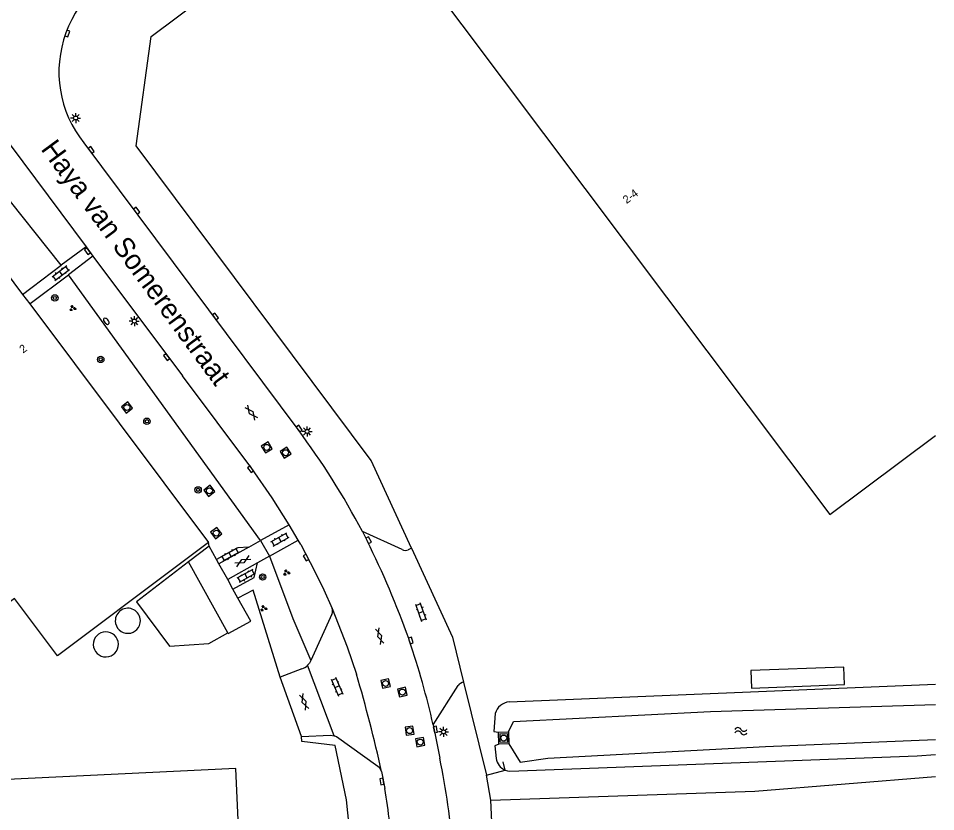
# Model space of a CAD drawing. Extents: x 126000 to 131009, y 393000 to 395500.
# Drawn here: x 130885.3 to 131000, y 393823.1 to 393922.3 of the extents above; entities that cross this region are included whole.
import ezdxf

# ---------------------------------------------------------------- set-up
doc = ezdxf.new("R2010")
doc.units = 0
for name, color, linetype in [('gg-afsc-hekwerk', 7, 'Continuous'), ('gg-anno-huisnummerreeks BGT', 7, 'Continuous'), ('gg-anno-openbare ruimte label', 7, 'Continuous'), ('gg-bbg-bijgebouw', 7, 'Continuous'), ('gg-bbg-gedigitaliseerde bebouwing', 7, 'Continuous'), ('gg-bbg-gedigitaliseerde bijgebouw', 7, 'Continuous'), ('gg-bbg-hoofdgebouw', 7, 'Continuous'), ('gg-bbg-luifel en loopbrug', 7, 'Continuous'), ('gg-bbg-opslagtank', 7, 'Continuous'), ('gg-knt-verharding', 7, 'Continuous'), ('gg-kntw-bovenkant insteek waterloop', 7, 'Continuous'), ('gg-kntw-waterlijn', 7, 'Continuous'), ('gg-kwrk-uitstroombak niveau min 01', 7, 'Continuous'), ('gt-grn-groengrens', 7, 'Continuous'), ('gt-grn-vlakafsluiter', 7, 'Continuous'), ('gt-symb-boom', 7, 'Continuous'), ('gt-symb-brandkraan', 7, 'Continuous'), ('gt-symb-gesloten verharding', 7, 'Continuous'), ('gt-symb-groenvak', 7, 'Continuous'), ('gt-symb-klinker verharding', 7, 'Continuous'), ('gt-symb-kolk', 7, 'Continuous'), ('gt-symb-lichtmast', 7, 'Continuous'), ('gt-symb-rioolschacht', 7, 'Continuous'), ('gt-symb-watersymbool', 7, 'Continuous')]:
    doc.layers.add(name, color=color, linetype=linetype)

# ---------------------------------------------------------------- blocks, each defined once
blk = doc.blocks.new('gt0-BOOM')
at = {"layer": 'gt-symb-boom'}
for radius in [0.4, 0.2]:
    blk.add_circle((0, 0), radius, dxfattribs=at)
blk = doc.blocks.new('gt0-KL1')
at = {"layer": 'gt-symb-klinker verharding'}
for p, q in [((-1.15, 0.3), (1.15, 0.3)), ((-1, -0.3), (-1, 0.3)), ((-0.5, 0.3), (-0.5, 0.45)), ((0, -0.3), (0, 0.3)), ((0.5, 0.3), (0.5, 0.45)), ((1, -0.3), (1, 0.3)), ((-1.15, -0.3), (1.15, -0.3)), ((-0.5, -0.45), (-0.5, -0.3)), ((0.5, -0.45), (0.5, -0.3))]:
    blk.add_line(p, q, dxfattribs=at)
blk = doc.blocks.new('gt0-KOLK')
at = {"layer": 'gt-symb-kolk'}
blk.add_lwpolyline([(0, 0), (0.38, 0), (0.38, 0.4), (-0.37, 0.4), (-0.37, 0), (0, 0)], dxfattribs=at)
blk = doc.blocks.new('gt0-GRVAK')
at = {"layer": 'gt-symb-groenvak'}
for p, q in [((-0.11, 0.19), (-0.23, 0.24)), ((-0.18, 0.15), (0.09, 0.15)), ((-0.09, 0.21), (-0.16, 0.32)), ((-0.05, 0.21), (-0.05, 0.39)), ((0, 0.21), (0.06, 0.32)), ((0.01, 0.19), (0.13, 0.24)), ((0.26, -0.05), (0.2, 0.06)), ((0.3, -0.05), (0.3, 0.13)), ((0.35, -0.05), (0.41, 0.06)), ((-0.25, -0.23), (-0.36, -0.18)), ((-0.32, -0.26), (-0.05, -0.26)), ((-0.23, -0.21), (-0.29, -0.1)), ((-0.18, -0.2), (-0.18, -0.02)), ((-0.14, -0.21), (-0.07, -0.1)), ((-0.12, -0.23), (0, -0.18)), ((0.24, -0.07), (0.12, -0.02)), ((0.17, -0.11), (0.44, -0.11)), ((0.37, -0.07), (0.49, -0.02))]:
    blk.add_line(p, q, dxfattribs=at)
blk = doc.blocks.new('gt0-LMAST')
at = {"layer": 'gt-symb-lichtmast'}
for p, q in [((-0.18, 0.17), (-0.45, 0.44)), ((0, 0.25), (0, 0.62)), ((0.17, 0.17), (0.44, 0.44)), ((-0.25, 0), (-0.63, 0)), ((-0.18, -0.18), (-0.45, -0.45)), ((0, -0.25), (0, -0.63)), ((0.44, -0.45), (0.17, -0.18)), ((0.25, 0), (0.62, 0))]:
    blk.add_line(p, q, dxfattribs=at)
blk.add_circle((0, 0), 0.25, dxfattribs=at)
blk = doc.blocks.new('gt0-RS')
at = {"layer": 'gt-symb-rioolschacht'}
blk.add_lwpolyline([(-0.5, -0.5), (0.5, -0.5), (0.5, 0.5), (-0.5, 0.5)], close=True, dxfattribs=at)
blk.add_circle((0, 0), 0.375, dxfattribs=at)
blk = doc.blocks.new('gt0-GESVH1')
at = {"layer": 'gt-symb-gesloten verharding'}
for p, q in [((-0.99, -0.26), (0.01, 0.24)), ((0.01, -0.26), (-0.99, 0.24)), ((0.01, 0.24), (1.01, -0.26)), ((1.01, 0.24), (0.01, -0.26))]:
    blk.add_line(p, q, dxfattribs=at)
blk = doc.blocks.new('gt0-BR')
at = {"layer": 'gt-symb-brandkraan'}
for centre, radius, start, end in [((-0.24, 0), 0.206, 107.5669, 252.4331), ((0.6, -2.66), 3, 106.892, 107.5669), ((0, -0.69), 0.938, 73.108, 106.892), ((-0.6, -2.66), 3, 72.4331, 73.108), ((0.24, 0), 0.206, 287.567, 72.4331), ((0.6, 2.66), 3, 252.4331, 253.108), ((0, 0.69), 0.938, 253.108, 286.8921), ((-0.6, 2.66), 3, 286.8921, 287.567)]:
    blk.add_arc(centre, radius, start, end, dxfattribs=at)
blk = doc.blocks.new('gt0-WA')
at = {"layer": 'gt-symb-watersymbool'}
for centre, start, end in [((-0.32, 0.02), 28.0725, 151.9275), ((0.43, 0.42), 208.0725, 331.9275), ((-0.32, -0.43), 28.0725, 151.9275), ((0.43, -0.03), 208.0725, 331.9275)]:
    blk.add_arc(centre, 0.425, start, end, dxfattribs=at)

msp = doc.modelspace()

# ---------------------------------------------------------------- linework, layer by layer
at = {"layer": 'gg-afsc-hekwerk'}
for p, q in [((130914.69, 393850.82), (130912.79, 393849.83)), ((130914.69, 393850.82), (130912.79, 393849.83)), ((130918.07, 393839.94), (130914.69, 393850.82)), ((130918.07, 393839.94), (130914.69, 393850.82)), ((130920.73, 393832.5), (130918.07, 393839.94)), ((130940.99, 393839.33), (130943.87, 393827.7)), ((130946.19, 393828.33), (130945.94, 393829.34)), ((130943.87, 393827.7), (130946.19, 393828.31)), ((130946.19, 393828.31), (130946.19, 393828.33)), ((130946.19, 393828.31), (130946.19, 393828.33))]:
    msp.add_line(p, q, dxfattribs=at)
for points in [[(130934.5, 393856.07), (130929.46, 393867.05), (130900.06, 393906.37), (130901.95, 393920.04), (130918.07, 393932.13)], [(130934.5, 393856.07), (130939.6, 393844.96), (130940.99, 393839.33)], [(130913.16, 393702.71), (130926.15, 393794.24), (130927.46, 393806.86), (130927.41, 393814.49), (130926.36, 393824.6), (130924.93, 393831.41), (130920.76, 393831.91), (130920.73, 393832.5)], [(130944.4, 393824.57), (130977.41, 393825.69), (131000, 393827.51)], [(130997.76, 393738.55), (130946.21, 393736.43), (130940.69, 393738.86), (130938.4, 393740.84), (130937.49, 393743.7), (130945.22, 393806.53), (130944.4, 393824.57)]]:
    msp.add_lwpolyline(points, dxfattribs=at)
at = {"layer": 'gg-bbg-bijgebouw'}
for p, q in [((130910.12, 393854.65), (130909.2, 393856.33)), ((130910.42, 393854.12), (130910.12, 393854.65)), ((130911.51, 393852.15), (130910.42, 393854.12)), ((130912.17, 393850.95), (130911.51, 393852.15)), ((130912.79, 393849.83), (130912.17, 393850.95)), ((130914.39, 393846.93), (130912.79, 393849.83))]:
    msp.add_line(p, q, dxfattribs=at)
at = {"layer": 'gg-bbg-gedigitaliseerde bebouwing'}
msp.add_lwpolyline([(130890.22, 393842.62), (130884.86, 393849.77), (130873.72, 393841.46), (130866.71, 393850.86)], dxfattribs=at)
at = {"layer": 'gg-bbg-gedigitaliseerde bijgebouw'}
for p, q in [((130909.2, 393856.33), (130906.62, 393854.35)), ((130911.52, 393845.49), (130906.62, 393854.35)), ((130911.58, 393845.39), (130914.39, 393846.93)), ((130911.58, 393845.39), (130911.52, 393845.49))]:
    msp.add_line(p, q, dxfattribs=at)
at = {"layer": 'gg-bbg-hoofdgebouw'}
for p, q in [((130872.68, 393905.41), (130885.87, 393887.8)), ((130885.87, 393887.8), (130886.76, 393886.61)), ((130886.76, 393886.61), (130909.12, 393856.77)), ((130909.12, 393856.77), (130905.11, 393853.77)), ((130905.11, 393853.77), (130890.22, 393842.62))]:
    msp.add_line(p, q, dxfattribs=at)
for points in [[(131000, 393987.17), (130930.57, 393935.13), (130986.79, 393860.26), (131000, 393870.15)], [(130802.57, 393751.42), (130803.26, 393736.2), (130813.98, 393736.69), (130814.21, 393731.65), (130813.5, 393731.62), (130813.68, 393728.03), (130814.39, 393728.06), (130814.72, 393720.63), (130827.08, 393721.21), (130826.62, 393731.74), (130827.33, 393731.77), (130827.32, 393732.26), (130826.62, 393732.22), (130826.39, 393737.27), (130913.59, 393741.23), (130912.89, 393756.45), (130915.77, 393756.61), (130912.51, 393828.52), (130776.64, 393821.98)]]:
    msp.add_lwpolyline(points, dxfattribs=at)
at = {"layer": 'gg-bbg-luifel en loopbrug'}
for points in [[(130906.62, 393854.35), (130900.1, 393849.36), (130904.24, 393843.8), (130909.16, 393844.14), (130911.52, 393845.49)], [(130976.99, 393838.58), (130988.59, 393839.01), (130988.51, 393841.19), (130976.91, 393840.76), (130976.99, 393838.58)]]:
    msp.add_lwpolyline(points, dxfattribs=at)
at = {"layer": 'gg-bbg-opslagtank'}
for centre, start, end in [((130899.03, 393846.99), 1.5368, 181.5744), ((130899.03, 393846.99), 181.5734, 1.5378), ((130896.28, 393844.04), 1.4819, 181.4819), ((130896.28, 393844.04), 181.4819, 1.4819)]:
    msp.add_arc(centre, 1.57, start, end, dxfattribs=at)
at = {"layer": 'gg-knt-verharding'}
for p, q in [((130880.63, 393911.43), (130893.8, 393893.76)), ((130893.53, 393906.76), (130920.29, 393870.91)), ((130893.8, 393893.76), (130890.71, 393891.44)), ((130893.8, 393893.76), (130894.67, 393892.59)), ((130894.67, 393892.59), (130891.6, 393890.26)), ((130894.67, 393892.59), (130905.86, 393877.64)), ((130885.87, 393887.8), (130890.71, 393891.44)), ((130886.83, 393886.66), (130891.6, 393890.26)), ((130886.83, 393886.66), (130886.76, 393886.61)), ((130919.2, 393858.99), (130915.63, 393857.01)), ((130920.33, 393857.05), (130919.2, 393858.99)), ((130933.3, 393855.91), (130928.35, 393858.14)), ((130928.35, 393858.14), (130928.94, 393856.98)), ((130914.15, 393856.19), (130915.63, 393857.01)), ((130915.63, 393857.01), (130916.74, 393855.05)), ((130916.74, 393855.05), (130920.33, 393857.05)), ((130920.64, 393856.54), (130920.33, 393857.05)), ((130914.15, 393856.19), (130910.42, 393854.12)), ((130934.5, 393856.07), (130934.07, 393855.88)), ((130916.74, 393855.05), (130915.24, 393854.22)), ((130915.24, 393854.22), (130911.51, 393852.15)), ((130924.53, 393847.83), (130921.89, 393842.04)), ((130934.12, 393844.76), (130934.21, 393844.48)), ((130920.79, 393840.97), (130918.07, 393839.94)), ((130924.83, 393832.62), (130921.5, 393841.42)), ((130937.19, 393833.99), (130940.3, 393838.91)), ((130937.19, 393833.99), (130938.01, 393829.82)), ((130930.73, 393828.15), (130931.14, 393826.01))]:
    msp.add_line(p, q, dxfattribs=at)
for points in [[(130919.2, 393858.99), (130917.08, 393862.37), (130914.54, 393866.05), (130905.86, 393877.64)], [(130914.15, 393856.19), (130912.77, 393856.11), (130910.12, 393854.65)], [(130920.64, 393856.54), (130922.42, 393853.15), (130923.51, 393850.85), (130924.56, 393848.53)], [(130912.17, 393850.95), (130914.83, 393852.41), (130915.24, 393854.22)], [(130924.56, 393848.53), (130926.45, 393843.74), (130927.6, 393840.31)], [(130921.89, 393842.04), (130921.73, 393841.71), (130921.5, 393841.42)], [(130920.73, 393832.5), (130924.36, 393832.69), (130924.83, 393832.62)], [(130930.29, 393828.78), (130925.09, 393832.46), (130924.83, 393832.62)]]:
    msp.add_lwpolyline(points, dxfattribs=at)
for centre, radius, start, end in [((130905.36, 393915.41), 14.96, 105.0044, 160.1172), ((130904.44, 393915.59), 14.03, 159.5102, 218.9991), ((130842.37, 393812.78), 97.22, 27.8134, 36.7203), ((130825.34, 393805.85), 115.54, 19.6811, 26.2708), ((130933.71, 393856.64), 0.842, 241.1761, 295.5465), ((130923.67, 393848.21), 0.946, 335.9963, 19.5985), ((130837.92, 393811.49), 101.79, 12.7664, 18.9094), ((130920.02, 393842.97), 2.15, 291.167, 313.5859), ((130763.9, 393791.64), 170.78, 12.3407, 16.5569), ((130941.39, 393837.89), 1.49, 105.5705, 137.0132), ((130849.13, 393811.37), 90.78, 4.2183, 11.7242), ((130929.72, 393827.9), 1.04, 13.4188, 56.9307), ((130855.75, 393812.77), 76.54, 3.537, 9.9569)]:
    msp.add_arc(centre, radius, start, end, dxfattribs=at)
at = {"layer": 'gg-kntw-bovenkant insteek waterloop'}
msp.add_line((130946.71, 393836.86), (131000, 393839.05), dxfattribs=at)
for points in [[(130944.94, 393835.38), (130944.76, 393833.15), (130945.34, 393833.06)], [(130945.41, 393831.58), (130944.89, 393831.36), (130945.06, 393829.78)], [(130946.19, 393828.33), (130946.49, 393828.24), (130946.79, 393828.2), (130997.67, 393830.11), (131000, 393830.27)]]:
    msp.add_lwpolyline(points, dxfattribs=at)
for centre, radius, start, end in [((130946.89, 393834.84), 2.02, 95.2701, 164.5262), ((130946.86, 393830.02), 1.81, 187.3661, 248.1594)]:
    msp.add_arc(centre, radius, start, end, dxfattribs=at)
at = {"layer": 'gg-kntw-waterlijn'}
for points in [[(130946.62, 393833.09), (130947.25, 393834.39), (130971.86, 393835.65), (131000, 393836.51)], [(130946.66, 393831.62), (130948.06, 393829.32), (130951.53, 393829.82), (130978.72, 393831.27), (131000, 393832.14)]]:
    msp.add_lwpolyline(points, dxfattribs=at)
at = {"layer": 'gg-kwrk-uitstroombak niveau min 01'}
for p, q in [((130945.34, 393833.06), (130946.62, 393833.09)), ((130945.41, 393831.58), (130945.34, 393833.06)), ((130946.62, 393833.09), (130946.66, 393831.62)), ((130946.66, 393831.62), (130945.41, 393831.58))]:
    msp.add_line(p, q, dxfattribs=at)
at = {"layer": 'gt-grn-groengrens'}
for p, q in [((130890.71, 393891.44), (130876.99, 393908.67)), ((130915.63, 393857.01), (130891.6, 393890.26)), ((130944.4, 393824.57), (130943.87, 393827.7))]:
    msp.add_line(p, q, dxfattribs=at)
msp.add_lwpolyline([(130916.74, 393855.05), (130919.64, 393847.26), (130921.89, 393842.04)], dxfattribs=at)
at = {"layer": 'gt-grn-vlakafsluiter'}
msp.add_line((130909.2, 393856.33), (130909.12, 393856.77), dxfattribs=at)

# ---------------------------------------------------------------- block references
at = {"layer": 'gt-symb-boom'}
for p, rotation in [((130889.9, 393887.36), 36.743796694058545), ((130895.64, 393879.67), 36.74379669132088), ((130901.41, 393871.94), 36.743796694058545), ((130907.81, 393863.36), 36.743796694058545)]:
    msp.add_blockref('gt0-BOOM', p, dxfattribs=dict(at, rotation=rotation))
msp.add_blockref('gt0-BOOM', (130915.88, 393852.46), dxfattribs=at)
at = {"layer": 'gt-symb-brandkraan', "rotation": 129.27731148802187}
msp.add_blockref('gt0-BR', (130896.33, 393884.45), dxfattribs=at)
at = {"layer": 'gt-symb-gesloten verharding'}
for p, rotation in [((130914.45, 393873.03), -52.39646300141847), ((130913.43, 393854.44), -150.9231364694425), ((130930.5, 393845.05), 107.45655813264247), ((130921.06, 393836.87), -69.1353388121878)]:
    msp.add_blockref('gt0-GESVH1', p, dxfattribs=dict(at, rotation=rotation))
at = {"layer": 'gt-symb-groenvak'}
for p in [(130892.12, 393886.07), (130918.85, 393853.01), (130916, 393848.54)]:
    msp.add_blockref('gt0-GRVAK', p, dxfattribs=at)
at = {"layer": 'gt-symb-klinker verharding'}
for p, rotation in [((130890.65, 393890.47), 36.950127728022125), ((130918.04, 393857.15), 28.998977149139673), ((130911.78, 393855.26), -150.9231364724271), ((130913.81, 393852.6), -150.9231364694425), ((130935.69, 393848.06), 109.73854688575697), ((130925.18, 393838.75), -66.35749834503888)]:
    msp.add_blockref('gt0-KL1', p, dxfattribs=dict(at, rotation=rotation))
at = {"layer": 'gt-symb-kolk'}
for p, rotation in [((130891.29, 393920.5), -110.30124998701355), ((130894.29, 393905.75), -52.969610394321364), ((130899.96, 393898.16), -53.21030035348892), ((130894.14, 393893.31), 126.9157067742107), ((130909.82, 393884.94), -53.256203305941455), ((130904.04, 393880.08), 126.29695894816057), ((130920.29, 393870.91), -53.256203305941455), ((130914.53, 393866.05), 125.930518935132), ((130928.94, 393856.98), -63.127461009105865), ((130921.48, 393854.98), 117.64114231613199), ((130934.21, 393844.48), -71.87318748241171), ((130937.67, 393833.44), 102.17475113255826), ((130930.97, 393826.93), 100.71464389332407)]:
    msp.add_blockref('gt0-KOLK', p, dxfattribs=dict(at, rotation=rotation))
at = {"layer": 'gt-symb-lichtmast'}
for p in [(130892.51, 393909.86), (130899.84, 393884.46), (130921.44, 393870.66), (130938.49, 393833.1)]:
    msp.add_blockref('gt0-LMAST', p, dxfattribs=at)
at = {"layer": 'gt-symb-rioolschacht'}
for p, rotation in [((130898.92, 393873.66), -53.290465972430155), ((130916.4, 393868.67), -58.2010871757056), ((130918.74, 393868.01), -58.20108717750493), ((130909.22, 393863.24), -53.290465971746), ((130910.07, 393857.95), -53.256203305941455), ((130931.24, 393839.15), 13.243802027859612), ((130933.35, 393838.08), 13.243802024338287), ((130934.24, 393833.25), 97.93555037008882), ((130946.02, 393832.33), 89.59893609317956), ((130935.57, 393831.82), 100.25359802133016)]:
    msp.add_blockref('gt0-RS', p, dxfattribs=dict(at, rotation=rotation))
at = {"layer": 'gt-symb-watersymbool', "rotation": 180}
msp.add_blockref('gt0-WA', (130975.71, 393833.18), dxfattribs=at)

# ---------------------------------------------------------------- texts
at = {"layer": 'gg-anno-huisnummerreeks BGT'}
for s, p in [('2-4', (130961.37, 393899.09)), ('2', (130885.93, 393880.4))]:
    msp.add_text(s, height=1, rotation=36.9, dxfattribs=at).set_placement(p)
at = {"layer": 'gg-anno-openbare ruimte label'}
msp.add_text('Haya van Somerenstraat', height=2.5, rotation=306.4, dxfattribs=at).set_placement((130888.07, 393905.96))

doc.saveas('drawing.dxf')
